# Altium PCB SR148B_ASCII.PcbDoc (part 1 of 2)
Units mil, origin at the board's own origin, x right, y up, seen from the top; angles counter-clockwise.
Board outline 3900 x 2475 mil, 6 copper layers (Top Layer, Signal Layer 1, Signal Layer 2, Signal Layer 3, Signal Layer 4, Bottom Layer), stack 60.536 mil thick; 89 components, 26 nets, 178 pads, 295 vias.
Unrouted connection lines stored in the file: 1.
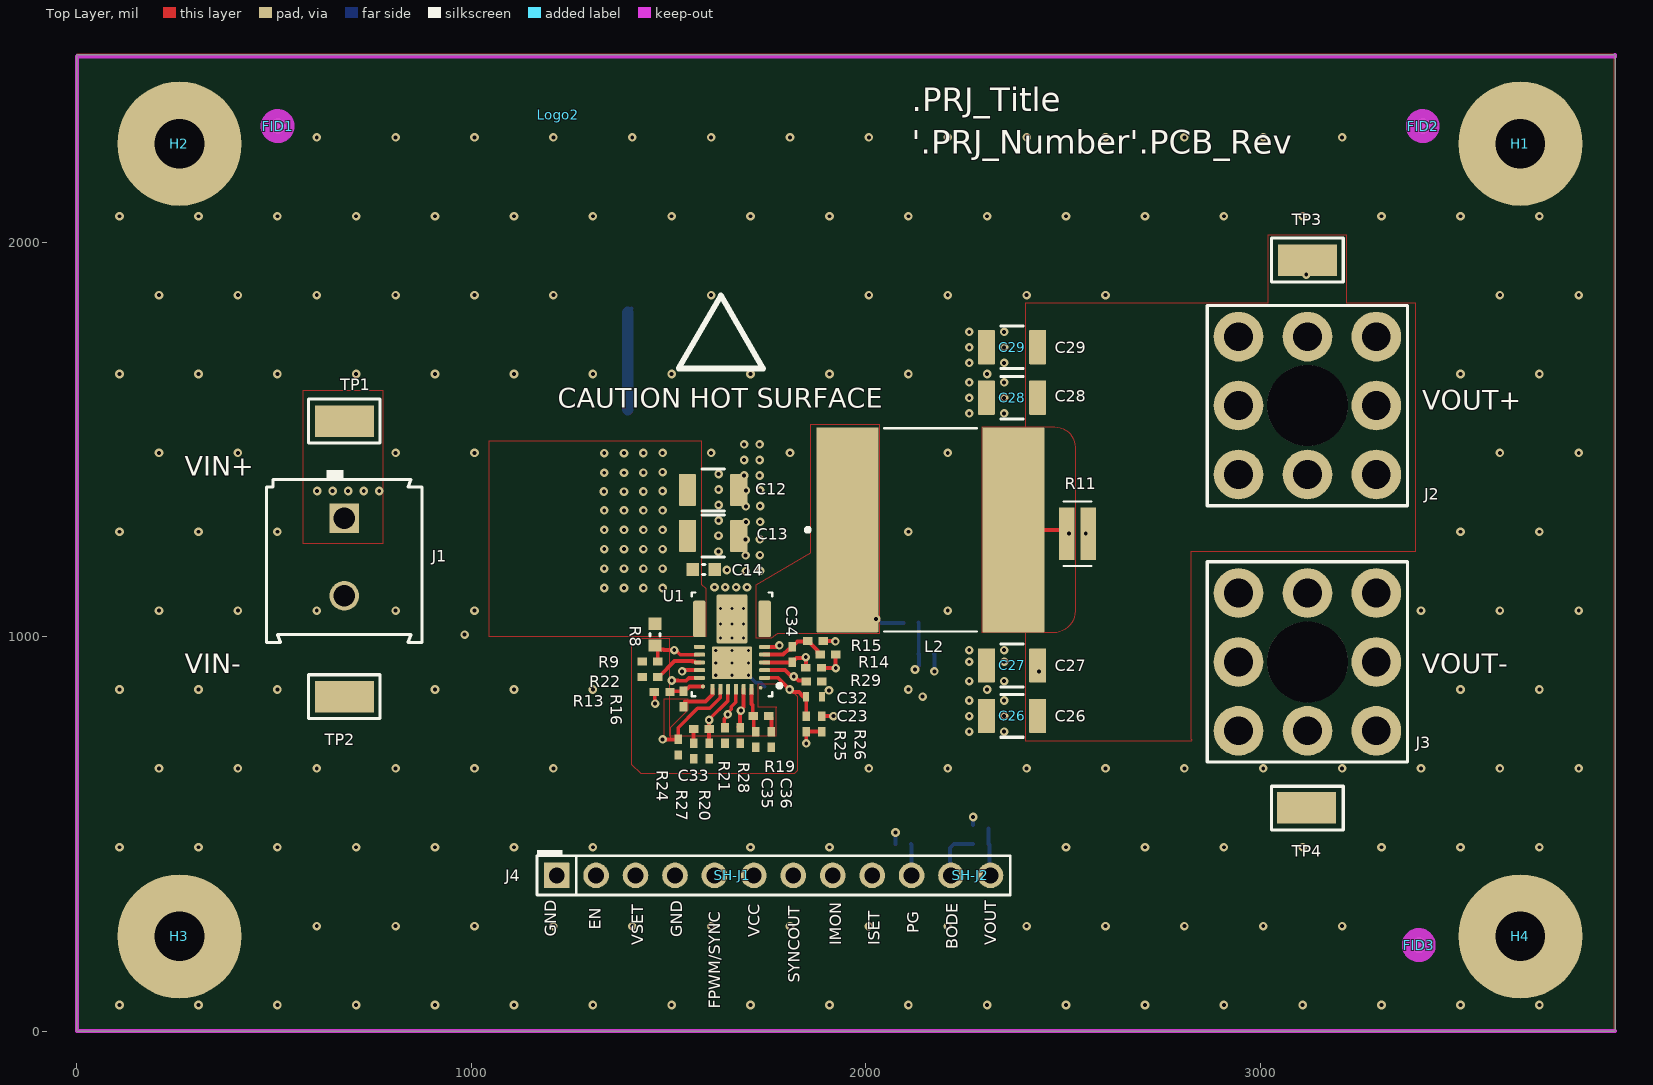
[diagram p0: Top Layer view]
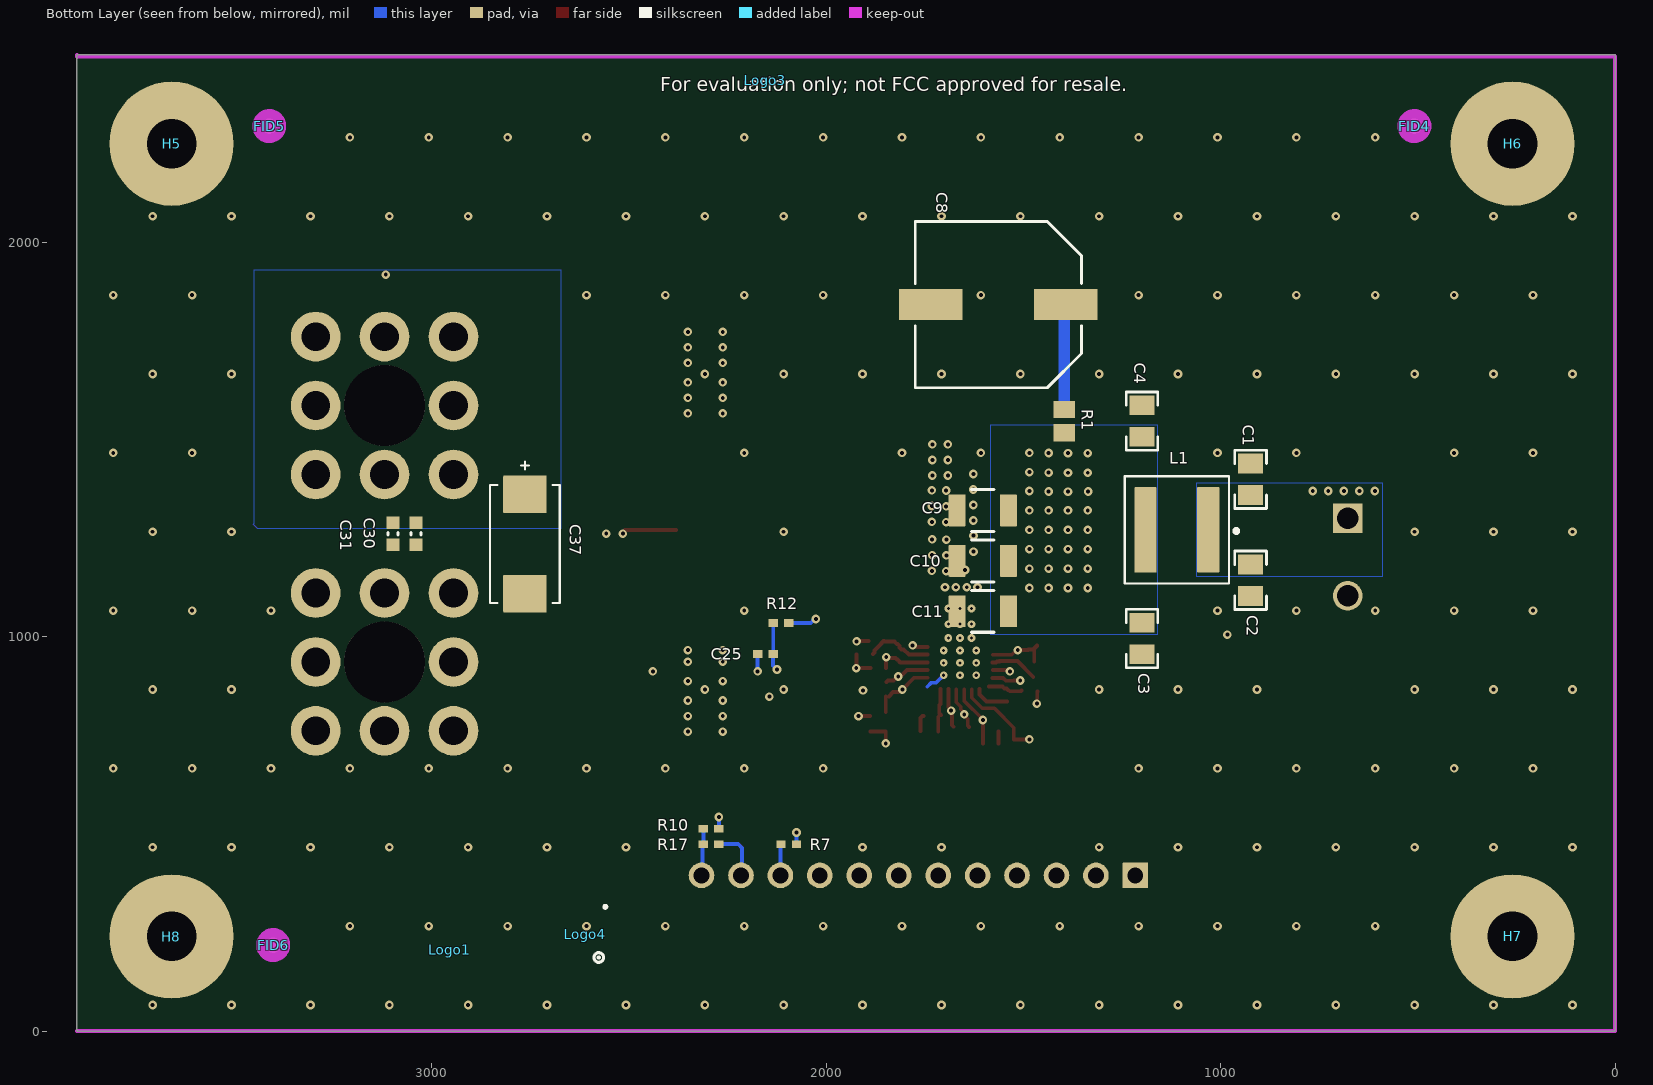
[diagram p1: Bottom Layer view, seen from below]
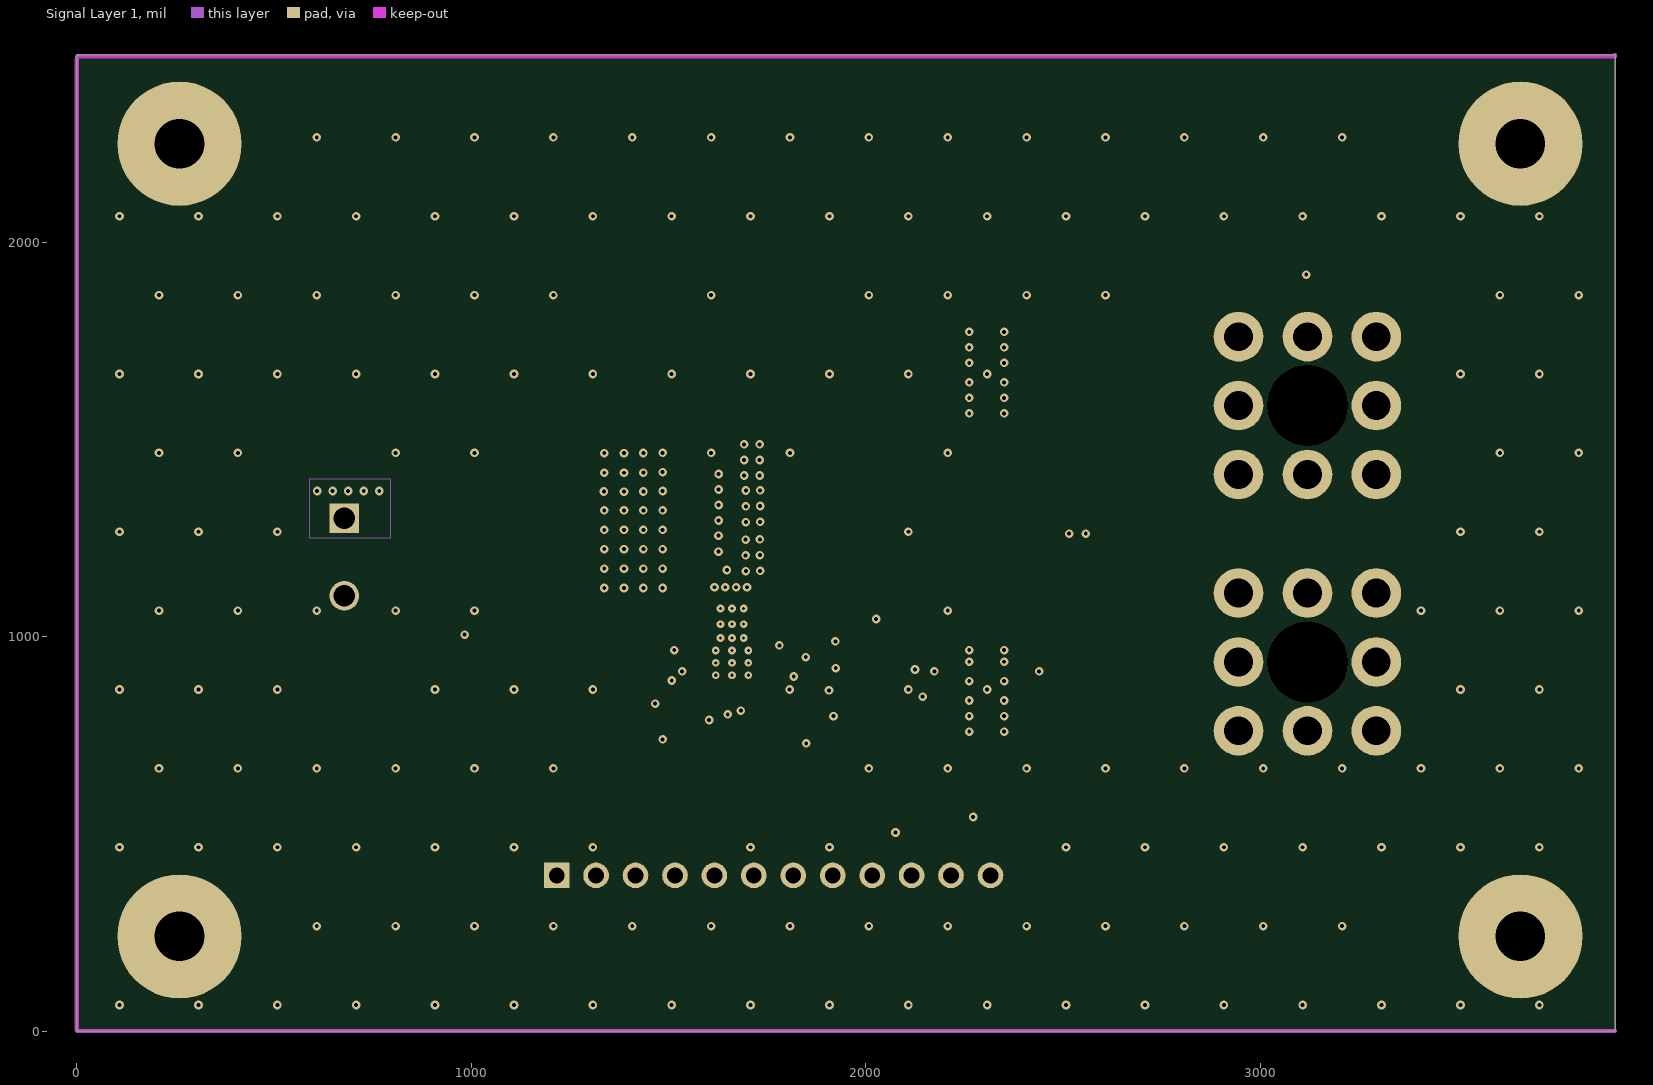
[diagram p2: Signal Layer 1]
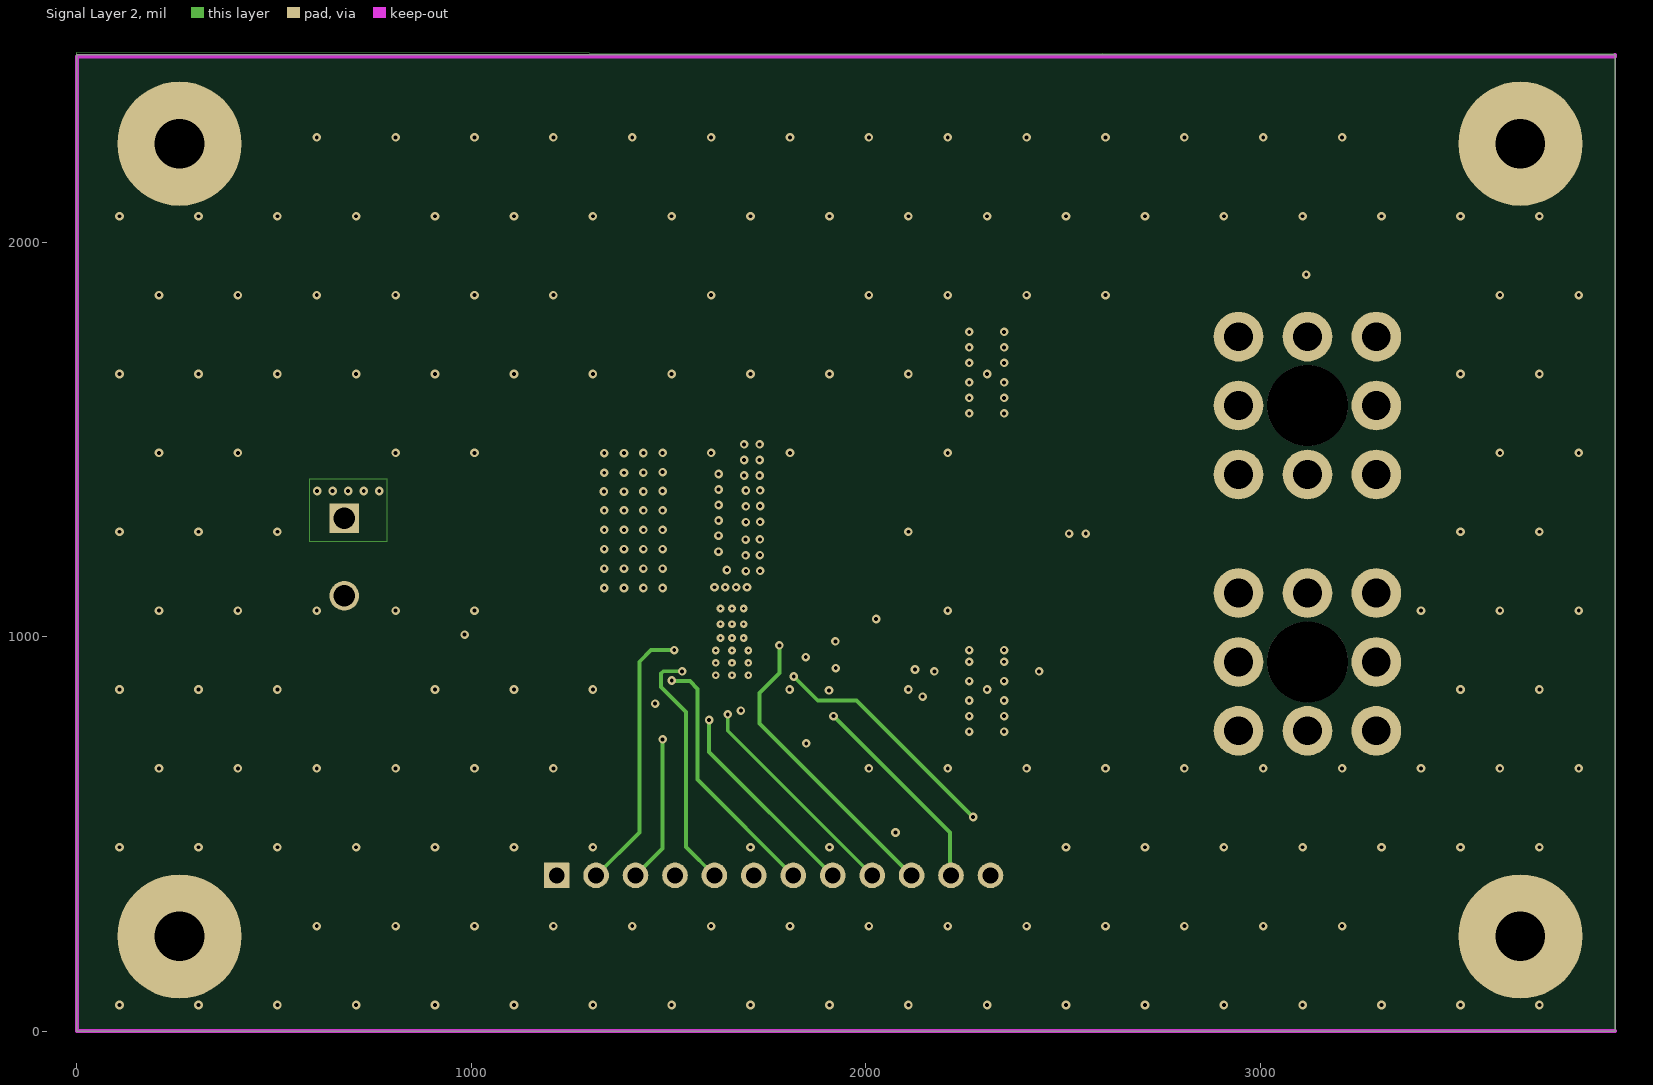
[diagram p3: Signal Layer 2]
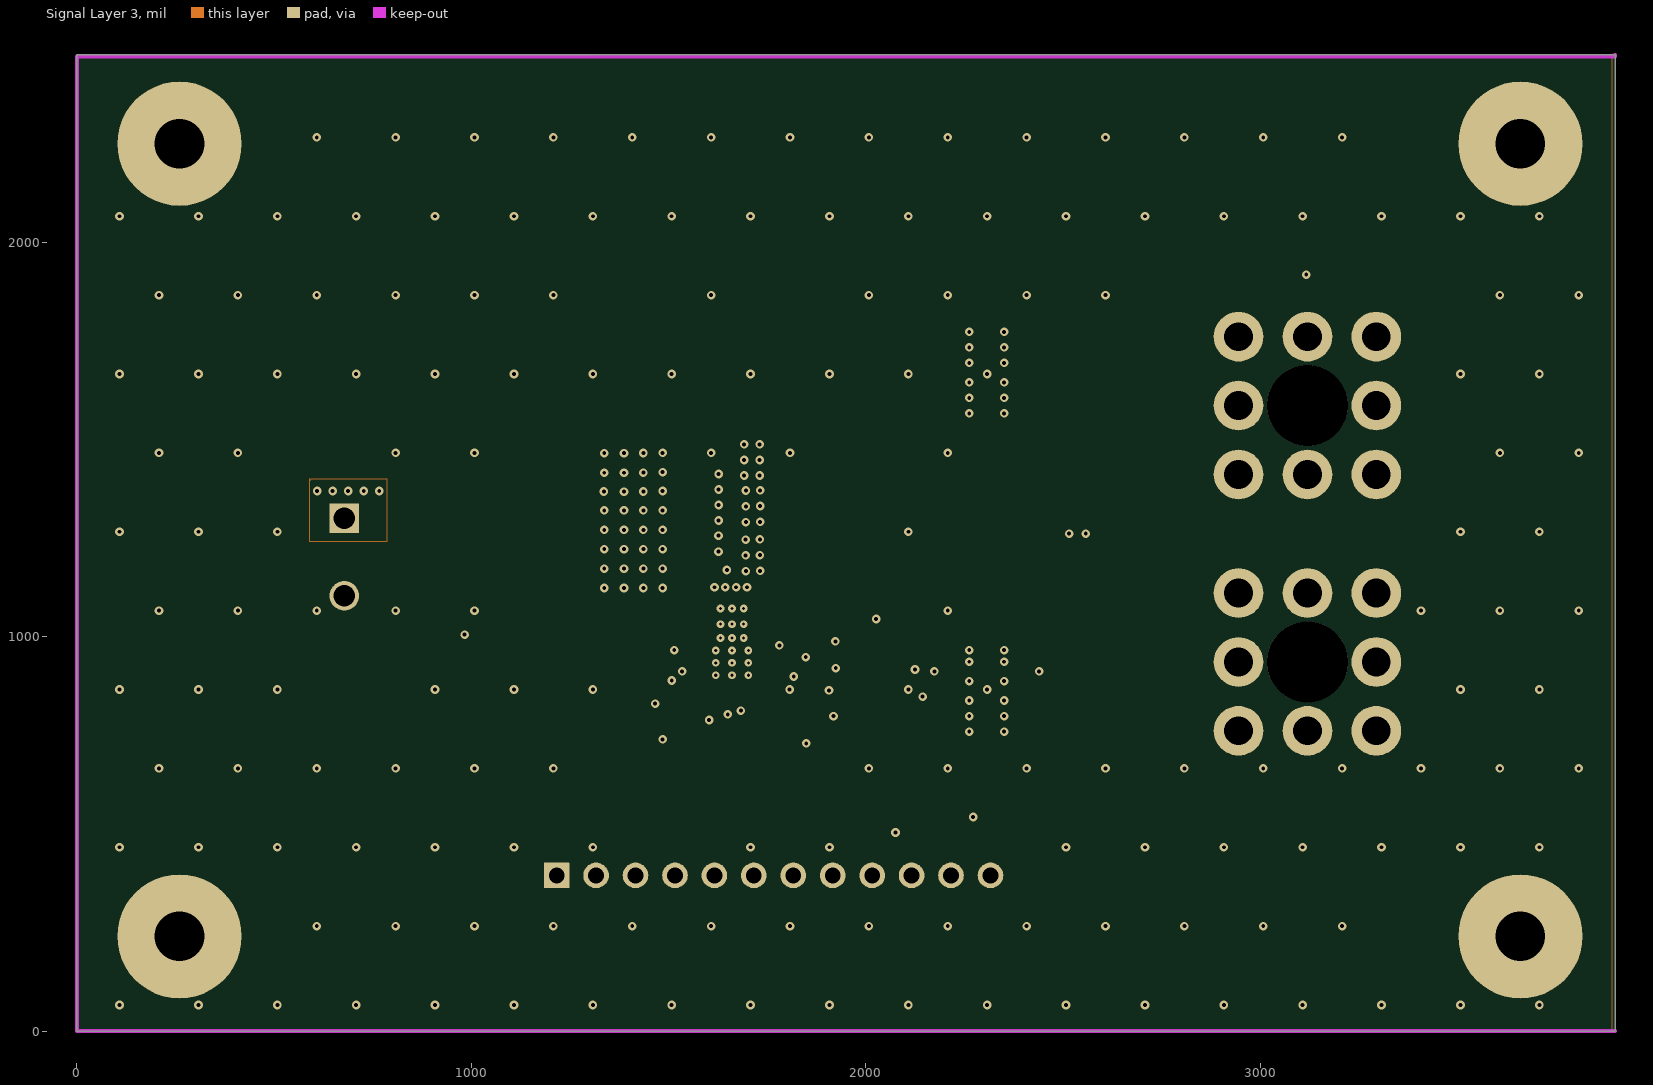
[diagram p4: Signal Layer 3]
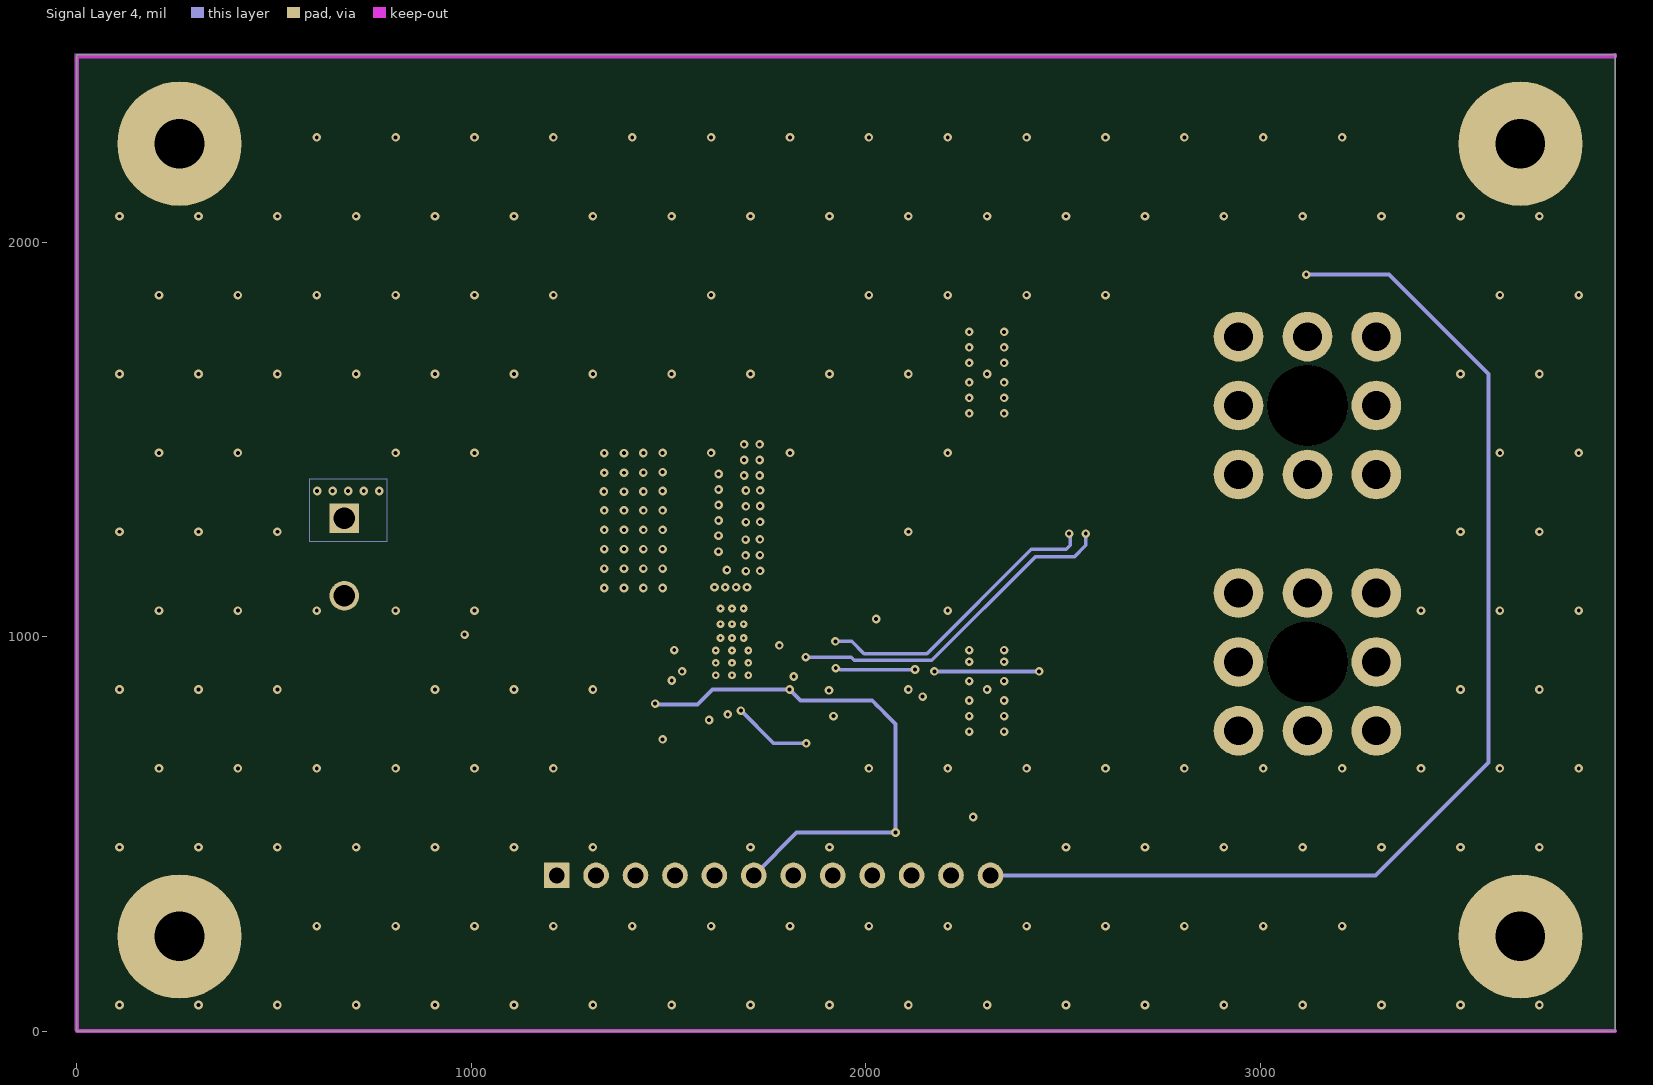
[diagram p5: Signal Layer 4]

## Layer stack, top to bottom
Top Solder: solder mask 0.4, Solder Resist, Dk 3.5
Top Layer: signal copper 2.756
Dielectric 1: prepreg 8, PP-006, Dk 4.1
Signal Layer 1: signal copper 2.756
Dielectric 2: prepreg 8, PP-006, Dk 4.1
Signal Layer 2: signal copper 2.756
Dielectric3: core 12, FR-4 High Tg, Dk 4.8
Signal Layer 3: signal copper 2.756
Dielectric 4: prepreg 8, PP-006, Dk 4.1
Signal Layer 4: signal copper 2.756
Dielectric 5: prepreg 8, PP-006, Dk 4.1
Bottom Layer: signal copper 2.756
Bottom Solder: solder mask 0.4, Solder Resist, Dk 3.5

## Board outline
0,0 3900,0 3900,2475 0,2475

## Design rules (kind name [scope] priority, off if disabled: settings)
AcuteAngle [All] p0: scope1count=1 scope1_0_kind=Board scope1_0_value=Board scope2count=1 scope2_0_kind=Board scope2_0_value=Board commentlength=0 minimum=4.50000000000000E+0001
AcuteAngle [All] p1: minimum=4.50000000000000E+0001 checktracksonly=FALSE
AssemblyTestPointUsage [All] p0: scope1count=1 scope1_0_kind=Board scope1_0_value=Board scope2count=1 scope2_0_kind=Board scope2_0_value=Board commentlength=0
AssemblyTestPointUsage [All] p1: valid=2
AssemblyTestpoint [All] p0: scope1count=1 scope1_0_kind=Board scope1_0_value=Board scope2count=1 scope2_0_kind=Board scope2_0_value=Board commentlength=0
BoardOutlineClearance [All] p0 off: scope1count=1 scope1_0_kind=Board scope1_0_value=Board scope2count=1 scope2_0_kind=Board scope2_0_value=Board commentlength=172 gap=40 // Protel DXP Scope 1 Expression Was: OnCopper and Not InComponentClass('Logo') and not InComponentClass('FiducialMark') and not InRegion(1000,500,4000,800) and not InPoly
BoardOutlineClearance BoardOutlineClearance_Poly [All] p0 off: scope1count=1 scope1_0_kind=Board scope1_0_value=Board scope2count=1 scope2_0_kind=Board scope2_0_value=Board commentlength=58 gap=25 // Protel DXP Scope 1 Expression Was: OnCopper and IsPoly
BoardOutlineClearance BoardOutlineClearance_MountingHoles [All] p0 off: scope1count=1 scope1_0_kind=Board scope1_0_value=Board scope2count=1 scope2_0_kind=Board scope2_0_value=Board commentlength=86 gap=39.37 // Protel DXP Scope 1 Expression Was: OnCopper and InComponentClass('Mounting Holes')
BoardOutlineClearance BoardOutlineClearance_MountingHoles [OnCopper and InComponentClass('Mounting Holes')] p1: gap=39.37 ignorepadtopadclearanceinfootprint=FALSE
BoardOutlineClearance BoardOutlineClearance_Poly [OnCopper and IsPoly] p2: gap=25 ignorepadtopadclearanceinfootprint=FALSE
BoardOutlineClearance [OnCopper and Not InComponentClass('Logo') and not InComponentClass('FiducialMark') and not InRegion(1000,500,4000,800) and not InPoly] p3: gap=40 ignorepadtopadclearanceinfootprint=FALSE
Clearance [All] p0 off: scope1count=1 scope1_0_kind=Board scope1_0_value=Board scope2count=1 scope2_0_kind=Layer scope2_0_value=TOP commentlength=75 gap=10 // Protel DXP Scope 1 Expression Was: InNamedPolygon('TOP_LAYER_GND_P823')
Clearance Clearance_1 [All] p0: scope1count=1 scope1_0_kind=Board scope1_0_value=Board scope2count=1 scope2_0_kind=Board scope2_0_value=Board commentlength=0 gap=7
Clearance Clearance_Keepouts [All] p0 off: scope1count=1 scope1_0_kind=Board scope1_0_value=Board scope2count=1 scope2_0_kind=Board scope2_0_value=Board commentlength=99 gap=10 // Protel DXP Scope 2 Expression Was: ((IsTrack Or IsArc) And Not InPoly) And IsFree and IsKeepOut
Clearance Clearance_Poly [All] p0 off: scope1count=1 scope1_0_kind=Board scope1_0_value=Board scope2count=1 scope2_0_kind=Board scope2_0_value=Board commentlength=48 gap=10 // Protel DXP Scope 1 Expression Was: InPolygon
Clearance Clearance_FiducialMark [All] p0 off: scope1count=1 scope1_0_kind=Board scope1_0_value=Board scope2count=1 scope2_0_kind=Board scope2_0_value=Board commentlength=81 gap=0 // Protel DXP Scope 2 Expression Was: IsPad and InComponentClass('FiducialMark')
Clearance [InNamedPolygon('TOP_LAYER_GND_P823') vs OnLayer('Top Layer')] p1: gap=10 ignorepadtopadclearanceinfootprint=FALSE
Clearance Clearance_FiducialMark [IsKeepOut and InComponentClass('FiducialMark') vs IsPad and InComponentClass('FiducialMark')] p2: gap=0 ignorepadtopadclearanceinfootprint=TRUE
Clearance Clearance_Keepouts [((IsTrack Or IsArc) And Not InPoly) And IsFree and IsKeepOut vs ((IsTrack Or IsArc) And Not InPoly) And IsFree and IsKeepOut] p3: gap=10 ignorepadtopadclearanceinfootprint=TRUE
Clearance Clearance_Poly [InPolygon] p4: gap=10 ignorepadtopadclearanceinfootprint=TRUE
Clearance Clearance_1 [All] p5: gap=7 ignorepadtopadclearanceinfootprint=TRUE except(0: SMDPad-Fill SMDPad-Poly SMDPad-Region)
ComponentClearance [All] p0: scope1count=1 scope1_0_kind=Board scope1_0_value=Board scope2count=1 scope2_0_kind=Board scope2_0_value=Board commentlength=0 gap=0 collisioncheckmode=3
ComponentClearance ComponentClearance_indInput [All] p0: scope1count=1 scope1_0_kind=Footprint scope1_0_value=HC2LP scope2count=1 scope2_0_kind=Footprint scope2_0_value=XAL8080 commentlength=0 gap=0 collisioncheckmode=3
ComponentClearance ComponentClearance_Inductors [All] p0: scope1count=1 scope1_0_kind=Footprint scope1_0_value=SER2915L scope2count=1 scope2_0_kind=Footprint scope2_0_value=IHLP-6767GZ commentlength=0 gap=0 collisioncheckmode=3
ComponentClearance ComponentClearance_MountingHoles_Headers [All] p0: scope1count=1 scope1_0_kind=Footprint scope1_0_value="NY PMS 440 0025 PH" scope2count=1 scope2_0_kind=Footprint scope2_0_value=Keystone_1902E commentlength=0 gap=0 collisioncheckmode=3
ComponentClearance ComponentClearanceConnectors [All] p0: scope1count=1 scope1_0_kind=Footprint scope1_0_value=FP-CB70-14-190_CONN_TERM_RECT_LUG-MFG scope2count=1 scope2_0_kind=Footprint scope2_0_value=Keystone_6096 commentlength=0 gap=0 collisioncheckmode=3
ComponentClearance ComponentClearance_THtoTH [All] p0 off: scope1count=1 scope1_0_kind=Board scope1_0_value=Board scope2count=1 scope2_0_kind=Board scope2_0_value=Board commentlength=54 gap=20 collisioncheckmode=3 // Protel DXP Scope 2 Expression Was: IsThruComponent
ComponentClearance ComponentClearance_THtoSMT [All] p0 off: scope1count=1 scope1_0_kind=Board scope1_0_value=Board scope2count=1 scope2_0_kind=Board scope2_0_value=Board commentlength=53 gap=0 collisioncheckmode=3 // Protel DXP Scope 2 Expression Was: IsSMTComponent
ComponentClearance ComponentClearance_SmallPassives [All] p0 off: scope1count=1 scope1_0_kind=Board scope1_0_value=Board scope2count=1 scope2_0_kind=Board scope2_0_value=Board commentlength=508 gap=10 collisioncheckmode=3 // Protel DXP Scope 2 Expression Was: HasFootprint('0201*') or HasFootprint('0402*') or HasFootprint('0508') or HasFootprint('0603*') or HasFootprint('0612') or HasFootprint('0805*') or HasFootprint('0815*') or HasFootprint('0830*') or HasFootprint('1206*') or HasFootprint('1210*') or HasFootprint('1808*') or HasFootprint('1812*') or HasFootprint('1825*') or HasFootprint('2010*') or HasFootprint('2220*') or HasFootprint('2225*') or HasFootprint('2512*') or HasFootprint('2728*') or HasFootprint('3518*')
ComponentClearance ComponentClearance_MountingHoles [All] p0: scope1count=1 scope1_0_kind=ComponentClass scope1_0_value="Mounting Holes" scope2count=1 scope2_0_kind=ComponentClass scope2_0_value="Mounting Holes" commentlength=0 gap=100 collisioncheckmode=3
ComponentClearance ComponentClearance_ScrewToNut [All] p0 off: scope1count=1 scope1_0_kind=Board scope1_0_value=Board scope2count=1 scope2_0_kind=Board scope2_0_value=Board commentlength=71 gap=5 collisioncheckmode=3 // Protel DXP Scope 2 Expression Was: (HasFootprint('Keystone_1902C'))
ComponentClearance ComponentClearance_Logo [All] p0: scope1count=1 scope1_0_kind=ComponentClass scope1_0_value=Logo scope2count=1 scope2_0_kind=Board scope2_0_value=Board commentlength=0 gap=30 collisioncheckmode=3
ComponentClearance ComponentClearance_Shunt [All] p0: scope1count=1 scope1_0_kind=ComponentClass scope1_0_value=Header scope2count=1 scope2_0_kind=ComponentClass scope2_0_value=Shunt commentlength=0 gap=0 collisioncheckmode=3
ComponentClearance ComponentClearance_MountingHoles_FiducialMarks [All] p0: scope1count=1 scope1_0_kind=ComponentClass scope1_0_value="Mounting Holes" scope2count=1 scope2_0_kind=ComponentClass scope2_0_value=FiducialMark commentlength=0 gap=50 collisioncheckmode=3
ComponentClearance ComponentClearance_MountingHoles_FiducialMarks [InComponentClass('Mounting Holes') vs InComponentClass('FiducialMark')] p1: gap=50 collisioncheckmode=3 verticalgap=10 showdistances=FALSE
ComponentClearance ComponentClearance_Shunt [InComponentClass('Header') vs InComponentClass('Shunt')] p2: gap=0 collisioncheckmode=3 verticalgap=0 showdistances=FALSE
ComponentClearance ComponentClearance_Logo [InComponentClass('Logo')] p3: gap=30 collisioncheckmode=3 verticalgap=10 showdistances=FALSE
ComponentClearance ComponentClearance_ScrewToNut [(HasFootprint('NY PMS 440 0025 PH')) vs (HasFootprint('Keystone_1902C'))] p4: gap=5 collisioncheckmode=3 verticalgap=10 showdistances=FALSE
ComponentClearance ComponentClearance_MountingHoles_Headers [HasFootprint('NY PMS 440 0025 PH') vs HasFootprint('Keystone_1902E')] p5: gap=0 collisioncheckmode=3 verticalgap=0 showdistances=FALSE
ComponentClearance ComponentClearance_MountingHoles [InComponentClass('Mounting Holes') vs InComponentClass('Mounting Holes')] p6: gap=100 collisioncheckmode=3 verticalgap=0 showdistances=FALSE
ComponentClearance ComponentClearance_SmallPassives [HasFootprint('0201*') or HasFootprint('0402*') or HasFootprint('0508') or HasFootprint('0603*') or HasFootprint('0612') or HasFootprint('0805*') or HasFootprint('0815*') or HasFootprint('0830*') or HasFootprint('1206*') or HasFootprint('1210*') or HasFootprint('1808*') or HasFootprint('1812*') or HasFootprint('1825*') or HasFootprint('2010*') or HasFootprint('2220*') or HasFootprint('2225*') or HasFootprint('2512*') or HasFootprint('2728*') or HasFootprint('3518*') vs HasFootprint('0201*') or HasFootprint('0402*') or HasFootprint('0508') or HasFootprint('0603*') or HasFootprint('0612') or HasFootprint('0805*') or HasFootprint('0815*') or HasFootprint('0830*') or HasFootprint('1206*') or HasFootprint('1210*') or HasFootprint('1808*') or HasFootprint('1812*') or HasFootprint('1825*') or HasFootprint('2010*') or HasFootprint('2220*') or HasFootprint('2225*') or HasFootprint('2512*') or HasFootprint('2728*') or HasFootprint('3518*')] p7: gap=10 collisioncheckmode=3 verticalgap=10 showdistances=FALSE
ComponentClearance ComponentClearance_THtoSMT [IsThruComponent vs IsSMTComponent] p8: gap=0 collisioncheckmode=3 verticalgap=0 showdistances=FALSE
ComponentClearance ComponentClearanceConnectors [HasFootprint('FP-CB70-14-190_CONN_TERM_RECT_LUG-MFG') vs HasFootprint('Keystone_6096')] p9: gap=0 collisioncheckmode=3 verticalgap=0 showdistances=FALSE
ComponentClearance ComponentClearance_Inductors [HasFootprint('SER2915L') vs HasFootprint('IHLP-6767GZ')] p10: gap=0 collisioncheckmode=3 verticalgap=0 showdistances=FALSE
ComponentClearance ComponentClearance_indInput [HasFootprint('HC2LP') vs HasFootprint('XAL8080')] p11: gap=0 collisioncheckmode=3 verticalgap=0 showdistances=FALSE
ComponentClearance ComponentClearance_THtoTH [IsThruComponent vs IsThruComponent] p12: gap=20 collisioncheckmode=3 verticalgap=30 showdistances=FALSE
ComponentClearance [All] p13: gap=0 collisioncheckmode=3 verticalgap=0 showdistances=TRUE
DiffPairsRouting [All] p0: scope1count=1 scope1_0_kind=Board scope1_0_value=Board scope2count=1 scope2_0_kind=Board scope2_0_value=Board commentlength=0
DiffPairsRouting [All] p1: maxlimit=100 minlimit=10 mostfreqgap=10 toplayer_minwidth=15 toplayer_maxwidth=15 toplayer_prefwidth=15 midlayer1_minwidth=15 midlayer1_maxwidth=15 midlayer1_prefwidth=15 midlayer2_minwidth=15 midlayer2_maxwidth=15 midlayer2_prefwidth=15 midlayer3_minwidth=15 midlayer3_maxwidth=15 midlayer3_prefwidth=15 midlayer4_minwidth=15 midlayer4_maxwidth=15 midlayer4_prefwidth=15 bottomlayer_minwidth=15 bottomlayer_maxwidth=15 bottomlayer_prefwidth=15 maxuncoupledlength=1000
FabricationTestPointUsage TestPointUsage [All] p0: scope1count=1 scope1_0_kind=Board scope1_0_value=Board scope2count=1 scope2_0_kind=Board scope2_0_value=Board commentlength=0 valid=2 allowmultiple=FALSE
FabricationTestPointUsage TestPointUsage [All] p1: valid=2 allowmultiple=FALSE
FabricationTestpoint Testpoint [All] p0: scope1count=1 scope1_0_kind=Board scope1_0_value=Board scope2count=1 scope2_0_kind=Board scope2_0_value=Board commentlength=0 side=3 testpointundercomponent=TRUE minsize=40 maxsize=100 preferedsize=60 minholesize=0 maxholesize=40 preferedholesize=32 testpointgrid=1
FabricationTestpoint Testpoint [All] p1: side=3 testpointundercomponent=TRUE minsize=40 maxsize=100 preferedsize=60 minholesize=0 maxholesize=40 preferedholesize=32 testpointgrid=1 allowsidetop=TRUE allowsidebottom=TRUE usegrid=TRUE gridtolerance=0.01
FanoutControl Fanout_Small [All] p0 off: scope1count=1 scope1_0_kind=Board scope1_0_value=Board scope2count=1 scope2_0_kind=Board scope2_0_value=Board commentlength=84 // Protel DXP Scope 1 Expression Was: (CompPinCount < 5)   Fanout_Small (Default Rule)
FanoutControl Fanout_Default [All] p0: scope1count=1 scope1_0_kind=Board scope1_0_value=Board scope2count=1 scope2_0_kind=Board scope2_0_value=Board commentlength=30 // Fanout_Default (Default Rule)
FanoutControl Fanout_SOIC [All] p0 off: scope1count=1 scope1_0_kind=Board scope1_0_value=Board scope2count=1 scope2_0_kind=Board scope2_0_value=Board commentlength=71 // Protel DXP Scope 1 Expression Was: IsSOIC   Fanout_SOIC (Default Rule)
FanoutControl Fanout_BGA [All] p0 off: scope1count=1 scope1_0_kind=Board scope1_0_value=Board scope2count=1 scope2_0_kind=Board scope2_0_value=Board commentlength=69 // Protel DXP Scope 1 Expression Was: IsBGA   Fanout_BGA (Default Rule)
FanoutControl Fanout_LCC [All] p0 off: scope1count=1 scope1_0_kind=Board scope1_0_value=Board scope2count=1 scope2_0_kind=Board scope2_0_value=Board commentlength=69 // Protel DXP Scope 1 Expression Was: IsLCC   Fanout_LCC (Default Rule)
FanoutControl Fanout_LCC [IsLCC] p1: bgadir=Out bgaviamode=Centered fanoutstyle=Auto fanoutdirection=Alternating viagrid=1 // Fanout_LCC (Default Rule)
FanoutControl Fanout_BGA [IsBGA] p2: bgadir=Out bgaviamode=Centered fanoutstyle=Auto fanoutdirection=Alternating viagrid=1 // Fanout_BGA (Default Rule)
Height [All] p0: scope1count=1 scope1_0_kind=Board scope1_0_value=Board scope2count=1 scope2_0_kind=Board scope2_0_value=Board commentlength=0
Height [All] p1: minheight=0 maxheight=1500 prefheight=500
HoleSize [All] p0: scope1count=1 scope1_0_kind=Board scope1_0_value=Board scope2count=1 scope2_0_kind=Board scope2_0_value=Board commentlength=0 absolutevalues=TRUE maxlimit=300 minlimit=7.87 maxpercent=80.000 minpercent=20.000
HoleSize [All] p1: absolutevalues=TRUE maxlimit=300 minlimit=7.87 maxpercent=80.000 minpercent=20.000
HoleToHoleClearance [All] p0: scope1count=1 scope1_0_kind=Board scope1_0_value=Board scope2count=1 scope2_0_kind=Board scope2_0_value=Board commentlength=0
LayerPairs [All] p0: scope1count=1 scope1_0_kind=Board scope1_0_value=Board scope2count=1 scope2_0_kind=Board scope2_0_value=Board commentlength=0 enforce=TRUE
MinimumAnnularRing [All] p0: scope1count=1 scope1_0_kind=Board scope1_0_value=Board scope2count=1 scope2_0_kind=Board scope2_0_value=Board commentlength=0 minimumring=0
MinimumAnnularRing MinimumAnnularRing_ThermalPadVias [All] p0 off: scope1count=1 scope1_0_kind=Board scope1_0_value=Board scope2count=1 scope2_0_kind=Board scope2_0_value=Board commentlength=63 minimumring=5.91 // Protel DXP Scope 1 Expression Was: IsVia and InAnyComponent
MinimumAnnularRing MinimumAnnularRing_ThermalPadVias [IsVia and InAnyComponent] p1: minimumring=5.91
MinimumAnnularRing [All] p2: minimumring=0
MinimumSolderMaskSliver [All] p0: scope1count=1 scope1_0_kind=Board scope1_0_value=Board scope2count=1 scope2_0_kind=Board scope2_0_value=Board commentlength=0
MinimumSolderMaskSliver MinimumSolderMaskSliver_Logo [All] p0: scope1count=1 scope1_0_kind=ComponentClass scope1_0_value=Logo scope2count=1 scope2_0_kind=ComponentClass scope2_0_value=Logo commentlength=0
MinimumSolderMaskSliver MinimumSolderMaskSliver_Logo [InComponentClass('Logo') vs InComponentClass('Logo')] p1: minsoldermaskwidth=0.7
MinimumSolderMaskSliver [All] p2: minsoldermaskwidth=3.94
NetAntennae [All] p0: scope1count=1 scope1_0_kind=Board scope1_0_value=Board scope2count=1 scope2_0_kind=Board scope2_0_value=Board commentlength=0
PasteMaskExpansion [All] p0: scope1count=1 scope1_0_kind=Board scope1_0_value=Board scope2count=1 scope2_0_kind=Board scope2_0_value=Board commentlength=0 expansion=0
PlaneClearance [All] p0: scope1count=1 scope1_0_kind=Board scope1_0_value=Board scope2count=1 scope2_0_kind=Board scope2_0_value=Board commentlength=0 clearance=10
PlaneClearance [All] p1: clearance=10
PlaneConnect [All] p0: scope1count=1 scope1_0_kind=Board scope1_0_value=Board scope2count=1 scope2_0_kind=Board scope2_0_value=Board commentlength=0 planeconnectstyle=Direct reliefexpansion=10 reliefentries=4 reliefconductorwidth=10 reliefairgap=10
PlaneConnect [All] p1: planeconnectstyle=Direct reliefexpansion=10 reliefentries=4 reliefconductorwidth=10 reliefairgap=10
PolygonConnect PolygonConnectStyle_1 [All] p0: scope1count=1 scope1_0_kind=Footprint scope1_0_value=TSW-112-07-G-S scope2count=1 scope2_0_kind=Board scope2_0_value=Board commentlength=0 connectstyle=Direct reliefconductorwidth=10 reliefentries=4 polygonreliefangle="90 Angle"
PolygonConnect [All] p0: scope1count=1 scope1_0_kind=Board scope1_0_value=Board scope2count=1 scope2_0_kind=Board scope2_0_value=Board commentlength=0 connectstyle=Direct reliefconductorwidth=10 reliefentries=4 polygonreliefangle="90 Angle"
PolygonConnect PolygonConnectStyle_1 [HasFootprint('TSW-112-07-G-S')] p1: connectstyle=Direct reliefconductorwidth=10 reliefentries=4 polygonreliefangle="90 Angle" airgapwidth=10
PolygonConnect [All] p2: connectstyle=Direct reliefconductorwidth=10 reliefentries=4 polygonreliefangle="90 Angle" airgapwidth=10
RoutingCorners [All] p0: scope1count=1 scope1_0_kind=Board scope1_0_value=Board scope2count=1 scope2_0_kind=Board scope2_0_value=Board commentlength=0 cornerstyle=45-Degree minsetback=100 maxsetback=100
RoutingLayers [All] p0: scope1count=1 scope1_0_kind=Board scope1_0_value=Board scope2count=1 scope2_0_kind=Board scope2_0_value=Board commentlength=0 top layer=Automatic mid layer 1=Automatic mid layer 2=Automatic mid layer 3=Automatic mid layer 4=Automatic bottom layer=Automatic
RoutingPriority [All] p0: scope1count=1 scope1_0_kind=Board scope1_0_value=Board scope2count=1 scope2_0_kind=Board scope2_0_value=Board commentlength=0
RoutingTopology [All] p0: scope1count=1 scope1_0_kind=Board scope1_0_value=Board scope2count=1 scope2_0_kind=Board scope2_0_value=Board commentlength=0 topology=Shortest
RoutingVias [All] p0: scope1count=1 scope1_0_kind=Board scope1_0_value=Board scope2count=1 scope2_0_kind=Board scope2_0_value=Board commentlength=0 holewidth=10 width=22 viastyle="Through Hole" minholewidth=7.87 minwidth=20 maxholewidth=40 maxwidth=65
RoutingVias ThermalPadVias [All] p0 off: scope1count=1 scope1_0_kind=Board scope1_0_value=Board scope2count=1 scope2_0_kind=Board scope2_0_value=Board commentlength=63 holewidth=7.87 width=19.68 viastyle="Through Hole" minholewidth=7.87 minwidth=19.68 maxholewidth=16 maxwidth=32 // Protel DXP Scope 1 Expression Was: IsVia and InAnyComponent
RoutingVias ThermalPadVias [IsVia and InAnyComponent] p1: holewidth=7.87 width=19.68 viastyle="Through Hole" minholewidth=7.87 minwidth=19.68 maxholewidth=16 maxwidth=32
RoutingVias [All] p2: holewidth=10 width=22 viastyle="Through Hole" minholewidth=7.87 minwidth=20 maxholewidth=40 maxwidth=65
ShortCircuit [All] p0: scope1count=1 scope1_0_kind=Net scope1_0_value=VOUT scope2count=1 scope2_0_kind=Net scope2_0_value=VOUT commentlength=0 allowed=TRUE
ShortCircuit [InNet('VOUT') vs InNet('VOUT')] p1: allowed=TRUE
SilkToBoardRegionClearance [All] p0: scope1count=1 scope1_0_kind=Board scope1_0_value=Board scope2count=1 scope2_0_kind=Board scope2_0_value=Board commentlength=0
SilkToSilkClearance [All] p0: scope1count=1 scope1_0_kind=Board scope1_0_value=Board scope2count=1 scope2_0_kind=Board scope2_0_value=Board commentlength=0
SilkToSilkClearance SilkToSilkClearance_Pb-FreeLogo [All] p0 off: scope1count=1 scope1_0_kind=Board scope1_0_value=Board scope2count=1 scope2_0_kind=Board scope2_0_value=Board commentlength=120 // Protel DXP Scope 2 Expression Was: (HasFootprint('Pb-Free_Overlay_Medium') OR HasFootprint('Pb-Free_Overlay_Small'))
SilkToSilkClearance SilkToSilkClearance_Pb-FreeLogo [(HasFootprint('Pb-Free_Overlay_Medium') OR HasFootprint('Pb-Free_Overlay_Small')) vs (HasFootprint('Pb-Free_Overlay_Medium') OR HasFootprint('Pb-Free_Overlay_Small'))] p1: silktosilkclearance=0
SilkToSilkClearance [All] p2: silktosilkclearance=3.94
SilkToSolderMaskClearance "Silk to Solder Mask Opening" [All] p0: scope1count=1 scope1_0_kind=Board scope1_0_value=Board scope2count=1 scope2_0_kind=Board scope2_0_value=Board commentlength=0
SilkToSolderMaskClearance SilkToComponentPadClearance [All] p0 off: scope1count=1 scope1_0_kind=Board scope1_0_value=Board scope2count=1 scope2_0_kind=Board scope2_0_value=Board commentlength=87 // Protel DXP Scope 1 Expression Was: (IsPad or IsFill or IsRegion) and InAnycomponent
SilkToSolderMaskClearance SilkToComponentPadClearance [(IsPad or IsFill or IsRegion) and InAnycomponent] p1: minsilkscreentomaskgap=5 clearancetoexposedcopper=TRUE
SilkToSolderMaskClearance "Silk to Solder Mask Opening" [All] p2: minsilkscreentomaskgap=3.94 clearancetoexposedcopper=FALSE
SolderMaskExpansion [All] p0: scope1count=1 scope1_0_kind=Board scope1_0_value=Board scope2count=1 scope2_0_kind=Board scope2_0_value=Board commentlength=0 expansion=1.97
SolderMaskExpansion [All] p1: expansion=1.97 istentingtop=FALSE
SupplyNets "Schematic Supply Nets_4" [All] p0: scope1count=1 scope1_0_kind=Net scope1_0_value=VIN scope2count=1 scope2_0_kind=Board scope2_0_value=Board commentlength=0 voltage=0.000
SupplyNets "Schematic Supply Nets_3" [All] p0: scope1count=1 scope1_0_kind=Net scope1_0_value=VCC scope2count=1 scope2_0_kind=Board scope2_0_value=Board commentlength=0 voltage=0.000
SupplyNets "Schematic Supply Nets_2" [All] p0: scope1count=1 scope1_0_kind=Net scope1_0_value=VOUT scope2count=1 scope2_0_kind=Board scope2_0_value=Board commentlength=0 voltage=0.000
SupplyNets "Schematic Supply Nets_1" [All] p0: scope1count=1 scope1_0_kind=Net scope1_0_value=AGND scope2count=1 scope2_0_kind=Board scope2_0_value=Board commentlength=0 voltage=0.000
SupplyNets "Schematic Supply Nets" [All] p0: scope1count=1 scope1_0_kind=Net scope1_0_value=GND scope2count=1 scope2_0_kind=Board scope2_0_value=Board commentlength=0 voltage=0.000
SupplyNets "Schematic Supply Nets_4" [InNet('VIN')] p1: voltage=0.000
SupplyNets "Schematic Supply Nets_3" [InNet('VCC')] p2: voltage=0.000
SupplyNets "Schematic Supply Nets_2" [InNet('VOUT')] p3: voltage=0.000
SupplyNets "Schematic Supply Nets_1" [InNet('AGND')] p4: voltage=0.000
SupplyNets "Schematic Supply Nets" [InNet('GND')] p5: voltage=0.000
UnRoutedNet [All] p0: scope1count=1 scope1_0_kind=Net scope1_0_value=PGND scope2count=1 scope2_0_kind=Board scope2_0_value=Board commentlength=0
UnRoutedNet [InNet('PGND')] p1: checkbadconnections=TRUE
UnpouredPolygon [All] p0: scope1count=1 scope1_0_kind=Board scope1_0_value=Board scope2count=1 scope2_0_kind=Board scope2_0_value=Board commentlength=0
Width [All] p0: scope1count=1 scope1_0_kind=Board scope1_0_value=Board scope2count=1 scope2_0_kind=Board scope2_0_value=Board commentlength=0 maxlimit=100 minlimit=6 preferedwidth=10
Width [All] p1: maxlimit=100 minlimit=6 preferedwidth=10 checkconnectedcopper=TRUE
14 further rules are at their usual default settings.

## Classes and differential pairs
component class FiducialMark: FID1 FID2 FID3 FID4 FID5 FID6
component class "Mounting Holes": H1 H2 H3 H4
component class Logo: Logo2
component class SR148B_Hardware: !PCB1 "CAUTION HOT SURFACE" FID1 FID2 FID3 FID4 FID5 FID6 H1 H2 H3 H4 H5 H6 H7 H8 Logo1 Logo2 Logo3 Logo4 SH-J1 SH-J2 ZZ1 ZZ2 ZZ3 ZZ4 ZZ5 ZZ6
component class AssemblyNote: ZZ1 ZZ2 ZZ3 ZZ4 ZZ5 ZZ6
component class SR148B: C1 C2 C3 C4 C8 C9 C10 C11 C12 C13 C14 C23 C25 C26 C27 C28 C29 C30 C31 C32 C33 C34 C35 C36 C37 J1 J2 J3 J4 L1 L2 R1 R7 R8 R9 R10 R11 R12 R13 R14 R15 R16 R17 R19 R20 R21 R22 R24 R25 R26 R27 R28 R29 TP1 TP2 TP3 TP4 U1 U2_S1
component class Header: J4

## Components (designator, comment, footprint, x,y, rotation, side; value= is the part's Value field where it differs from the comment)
C1 "GRM21BR72A474KA73L" 0805_HV 924,1398.95 r90 bottom
C2 "GRM21BR72A474KA73L" 0805_HV 924,1143.05 r270 bottom
C3 "GRM21BR72A474KA73L" 0805_HV 1199.59,995.41 r270 bottom
C4 "GRM21BR72A474KA73L" 0805_HV 1199.59,1546.59 r90 bottom
C8 "EEE-FK2A330P" SM_RADIAL_G 1563.76,1841.87 r0 bottom
C9 "GRM32EC72A106KE05L" FP-GRM32EC72A106KE05L_1210-MFG 1603.13,1320.21 r0 bottom
C10 "GRM32EC72A106KE05L" FP-GRM32EC72A106KE05L_1210-MFG 1603.13,1192.26 r0 bottom
C11 "GRM32EC72A106KE05L" FP-GRM32EC72A106KE05L_1210-MFG 1603.13,1064.31 r0 bottom
C12 "GRM32EC72A106KE05L" FP-GRM32EC72A106KE05L_1210-MFG 1613,1372 r0 top
C13 "GRM32EC72A106KE05L" FP-GRM32EC72A106KE05L_1210-MFG 1613,1255.53 r0 top
C14 "CGA3E2X8R2A103K080AD" 0603L 1589.29,1169.94 r0 top
C23 "GRT155C71A225KE13" 0402_070 1868.88,847.77 r0 top
C25 "CGA2B3X7R1E104K050BB" 0402L 2154,956.04 r0 bottom
C26 "GCM32EC71A476KE02K" FP-GCM32EC71A476KE02K_1210-MFG 2371,799 r0 top
C26 "CGA6P3X7R1E226M250AB" FP-CGA6P3X7R1E226M250AB_1210-MFG 2371,799 r0 top
C27 "GCM32EC71A476KE02K" FP-GCM32EC71A476KE02K_1210-MFG 2371,927 r0 top
C27 "CGA6P3X7R1E226M250AB" FP-CGA6P3X7R1E226M250AB_1210-MFG 2371,927 r0 top
C28 "CGA6P3X7R1E226M250AB" FP-CGA6P3X7R1E226M250AB_1210-MFG 2371,1606 r0 top
C28 "GCM32EC71A476KE02K" FP-GCM32EC71A476KE02K_1210-MFG 2371,1606 r0 top
C29 "CGA6P3X7R1E226M250AB" FP-CGA6P3X7R1E226M250AB_1210-MFG 2371,1734 r0 top
C29 "GCM32EC71A476KE02K" FP-GCM32EC71A476KE02K_1210-MFG 2371,1734 r0 top
C30 "C0603C104K5RACTU" 0603L 3040,1261 r270 bottom
C31 "C0603C104K5RACTU" 0603L 3099,1261 r270 bottom
C32 "CGA2B3X7R1E104K050BB" 0402L 1869,886 r0 top
C33 "CGA2B3X8R1H103K050BB" 0402L 1583.45,766 r0 top
C34 "CGA2B2C0G1H101J050BA" 0402L 1814,955 r270 top
C35 "CGA2B2C0G1H470J050BA" 0402L 1721,739.5 r270 top
C36 "GRM155R71H272KA01D" 0402L 1760.61,739.5 r270 top
C37 "ECASD61C107M012KA0" FP-ECASD61C107M012KA0_2917-MFG 2764,1235 r90 bottom
"CAUTION HOT SURFACE" "CAUTION HOT SURFACE" IEC_HotSurface_Small 1632.66,1772.97 r0 top
FID1 "Fiducial" Fiducial10-20 508.78,2294.74 r90 top
FID2 "Fiducial" Fiducial10-20 3412.32,2294.74 r90 top
FID3 "Fiducial" Fiducial10-20 3402.48,217.97 r90 top
FID4 "Fiducial" Fiducial10-20 508.78,2294.74 r90 bottom
FID5 "Fiducial" Fiducial10-20 3412.32,2294.74 r90 bottom
FID6 "Fiducial" Fiducial10-20 3402.48,217.97 r90 bottom
H1 "NY PMS 440 0025 PH" "NY PMS 440 0025 PH" 3660,2250 r0 top
H2 "NY PMS 440 0025 PH" "NY PMS 440 0025 PH" 260,2250 r0 top
H3 "NY PMS 440 0025 PH" "NY PMS 440 0025 PH" 260,240 r0 top
H4 "NY PMS 440 0025 PH" "NY PMS 440 0025 PH" 3660,240 r0 top
H5 "1902C" Keystone_1902E 3660,2250 r180 bottom
H6 "1902C" Keystone_1902E 260,2250 r180 bottom
H7 "1902C" Keystone_1902E 260,240 r180 bottom
H8 "1902C" Keystone_1902E 3660.63,239.37 r180 bottom
J1 "282856-2" TE_282856-2 677.94,1202.1 r270 top
J2 "74655095R" FP-74655095R_CONN_TERM_10MM0_10MM0-MFG 3120,1586 r0 top
J3 "74655095R" FP-74655095R_CONN_TERM_10MM0_10MM0-MFG 3120,936 r0 top
J4 "TSW-112-07-G-S" TSW-112-07-G-S 1766.3,394.69 r0 top
L1 "XGL6060-332MEC" FP-XGL6060-332MEC_SMT_6MM51_6MM71-MFG 1111.01,1271 r0 bottom
L2 "VCUD128T-4R7MS8" FP-VCUD128T-4R7MS8_SMT_IND_13MM3_12MM8-MFG 2164.16,1271 r0 top
Logo1 "CE Mark" CE_Mark_5mm 2954.99,206.33 r180 bottom
Logo2 "Texas Instruments" TI_Stacked_Overlay_Small 1220.47,2322.83 r0 top
Logo3 "FCC disclaimer" FCC_disclaimer 2155,2411 r180 bottom
Logo4 "WEEE logo" WEEE_Minimum 2610.87,244.86 r180 bottom
R1 "ERJ-6GEY0R00V" 0805L 1396.44,1546.59 r270 bottom
R7 "AC0402FR-07100KL" 0402L 2095.26,473.76 r180 bottom
R8 "RC0603FR-07200KL" 0603L 1465.34,1005.25 r90 top
R9 "ERJPA2F1002X" 0402L 1453,937.2 r0 top
R10 "CRCW04021R00FKED" 0402L 2292.11,513.13 r0 bottom
R11 "KRL3216E-C-R001-J-T5" FP-KRL3216E-C-R001-J-T5_0612-MFG 2537,1261 r0 top
R12 "ERJPA2F1002X" 0402L 2114.94,1034.78 r0 bottom
R13 "CRCW040254K9FKED" 0402L 1483.82,860 r180 top
R14 "RK73Z1ETTP" 0402L 1904,955 r0 top
R15 "ERJ-2RKF49R9X" 0402L 1873,989 r0 top
R16 "CRCW040254K9FKED" 0402L 1538.27,842.1 r90 top
R17 "ERJ-2RKF49R9X" 0402L 2292.11,473.76 r0 bottom
R19 "CRCW040211K0FKED" 0402L 1734.29,798.59 r180 top
R20 "CRCW04028K66FKED" 0402L 1603.13,709.98 r90 top
R21 "CRCW040290K9FKED" 0402L 1643,749.35 r90 top
R22 "CRCW040223K7FKED" 0402L 1453,897.63 r0 top
R24 "CRCW040290K9FKED" 0402L 1524.39,719.82 r90 top
R25 "RK73Z1ETTP" 0402L 1849.2,778.87 r90 top
R26 "CRCW040254K9FKED" 0402L 1888.57,778.87 r90 top
R27 "RK73Z1ETTP" 0402L 1563.76,709.98 r90 top
R28 "ERA-2AEB4991X" 0402L 1681.87,749.35 r90 top
R29 "AC0402FR-07100KL" 0402L 1868,921 r0 top
SH-J1 "M7582-05" Harwin_M7582-05 1662,395 r180 top
SH-J2 "M7582-05" Harwin_M7582-05 2265,395 r180 top
TP1 "5019" Keystone_5019#1 677.94,1546.59 r0 top
TP2 "5019" Keystone_5019#1 677.94,847.77 r0 top
TP3 "5019" Keystone_5019#1 3120,1955 r0 top
TP4 "5019" Keystone_5019#2 3120,565 r0 top
U1 "LMG708B0VBTR" VBT0022B-MFG 1661,979 r180 top
ZZ1 "This Assembly Note is for PCB labels only" AssemblyNoteLabel 19.68,3357.28 r0 top
ZZ2 "These assemblies are ESD sensitive, ESD precautions shall be observed." AssemblyNote 19.68,3257.28 r0 top
ZZ3 "These assemblies must be clean and free from flux and all contaminants. Use of no clean flux is not acceptable." AssemblyNote 19.68,3157.28 r0 top
ZZ4 "These assemblies must comply with workmanship standards IPC-A-610 Class 2, unless otherwise specified." AssemblyNote 19.68,3061.02 r0 top
ZZ5 "Install Shunt Jumper SH-J1 onto J4 Pins 5-6" AssemblyNote 19.68,2952.76 r0 top
ZZ6 "Install Shunt Jumper SH-J2 onto J4 Pins 11-12" AssemblyNote 22,2844 r0 top

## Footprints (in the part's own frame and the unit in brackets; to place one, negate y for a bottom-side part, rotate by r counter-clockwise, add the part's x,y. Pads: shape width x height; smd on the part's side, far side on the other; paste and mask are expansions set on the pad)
0402_070 [mil] "SMD, 2-Leads, Body 1.2x0.7mm, Height 0.7mm"
  rect 15x24 smd: 1(-20,0) 2(20,0)
0402L [mm] "0402 from SM-752 data"
  rect 0.6x0.5 smd: 1(-0.5,0) 2(0.5,0)
0603L [mm] "0603 from SM-752 data"
  rect 0.8x0.85 smd: 1(-0.7,0) 2(0.7,0)
  silkscreen extent -0.07,-0.33 0.07,0.33
0805_HV [mil] "0805 with 30mil clearance between pads"
  rect 50x63 smd: 1(-40,0) 2(40,0)
  silkscreen extent -74,-40 74,40
0805L [mm] "0805 from SM-752 data"
  rect 1.1x1.4 smd: 1(-0.75,0) 2(0.75,0)
AssemblyNote [mil] "Assembly Note"
AssemblyNoteLabel [mil] "Assembly Note for PCB Labels"
CE_Mark_5mm [mil] "Minimum text height for CE Mark"
FCC_disclaimer [mil]
Fiducial10-20 [mm]
  round 1 smd mask+0: 1(0,0)
  Top Layer keep-out circle w1.178: c0,0 r0.5
FP-74655095R_CONN_TERM_10MM0_10MM0-MFG [mm]
  round 3.2 hole 1.85 paste+0 mask+0: 1(-4.435,-4.435) 1(-4.435,0) 1(-4.435,4.435) 1(0,-4.435) 1(0,4.435) 1(4.435,-4.435) 1(4.435,0) 1(4.435,4.435)
  round 5.2 hole 5.2 unplated paste+0 mask+0: ""(0,0)
  silkscreen extent -6.45,-6.45 6.45,6.45
FP-CGA6P3X7R1E226M250AB_1210-MFG [mm]
  rrect9% 1.1x2.2 smd paste+0 mask+0: 1(-1.65,0) 2(1.65,0)
  silkscreen extent -0.72,-1.4 0.72,1.4
FP-ECASD61C107M012KA0_2917-MFG [mm] "Recommended Land Pattern"
  rrect4% 2.4x2.8 smd paste+0 mask+0: 1(-3.2,0) 2(3.2,0)
  silkscreen extent -3.8,-2.25 5.3,2.25
FP-GCM32EC71A476KE02K_1210-MFG [mm]
  rrect9% 1.1x2.05 smd paste+0 mask+0: 1(-1.65,0) 2(1.65,0)
  silkscreen extent -0.72,-1.35 0.72,1.35
FP-GRM32EC72A106KE05L_1210-MFG [mm]
  rrect9% 1.1x2.05 smd paste+0 mask+0: 1(-1.65,0) 2(1.65,0)
  silkscreen extent -0.72,-1.35 0.72,1.35
FP-KRL3216E-C-R001-J-T5_0612-MFG [mm] "Recommended Land Pattern"
  rrect10% 1x3.4 smd paste+0 mask+0: 1(-0.7,0) 2(0.7,0)
  silkscreen extent -0.9,-2.07 0.9,2.07
FP-VCUD128T-4R7MS8_SMT_IND_13MM3_12MM8-MFG [mm] "Recommended Land Pattern"
  rrect3% 4x13.2 smd paste+0 mask+0: 1(-5.35,0) 2(5.35,0)
  silkscreen extent -8.02,-6.55 2.98,6.55
FP-XGL6060-332MEC_SMT_6MM51_6MM71-MFG [mm]
  rrect7% 1.43x5.5 smd paste+0 mask+0: 1(-2.02,0) 2(2.02,0)
  silkscreen extent -3.95,-3.45 3.35,3.45
Harwin_M7582-05 [mil] "Single Operation 2.54mm Pitch Open Top Jumper Socket"
IEC_HotSurface_Small [mil]
  silkscreen extent -107,-93 107,92
Keystone_1902E [mil] "Hex Standoff, 4-40 threaded, nylon"
  round 1 on Mech4: 0(0,0)
Keystone_5019#1 [mm] "Test Point, Miniature, SMT"
  rect 3.8x2.03 smd: 1(0,0)
  silkscreen extent -2.31,-1.42 2.31,1.42
Keystone_5019#2 [mm] "Test Point, Miniature, SMT"
  rect 3.8x2.03 smd: 1(-0.05,0.015)
  silkscreen extent -2.31,-1.42 2.31,1.42
"NY PMS 440 0025 PH" [mm] "4-40 nylon screw and mounting hole"
  round 8 hole 3.2: 1(0,0)
SM_RADIAL_G [mm] "10 x 10.2mm:  Panasonic G"
  rect 4.1x2 smd: 1(-4.35,0) 2(4.35,0)
  silkscreen extent -5.35,-5.35 5.35,5.35
TE_282856-2 [mm] "TH, 2-Leads, Body 10x10mm, Pitch 5mm"
  rect 1.9x1.9 hole 1.4: 1(-2.5,0)
  round 1.9 hole 1.4: 2(2.5,0)
  silkscreen extent -5.61,-5 5.5,5
TI_Stacked_Overlay_Small [mil]
TSW-112-07-G-S [mm] "Samtec 100mil, 1x12, 230 mil above insulator"
  rrect6% 1.65x1.65 hole 1.016 mask+0: 1(-13.97,0)
  round 1.65 hole 1.016 mask+0: 2(-11.43,0) 3(-8.89,0) 4(-6.35,0) 5(-3.81,0) 6(-1.27,0) 7(1.27,0) 8(3.81,0) 9(6.35,0) 10(8.89,0) 11(11.43,0) 12(13.97,0)
  silkscreen extent -15.24,-1.27 15.24,1.65
VBT0022B-MFG [mm] "Recommended Land Pattern"
  round 0.234 smd paste+0 mask+0: 1(-1.837,2.762)
  rrect40% 0.7x0.25 smd paste+0 mask+0: 2(-2.1,2.125) 3(-2.1,1.625) 4(-2.1,1.125) 5(-2.1,0.625) 6(-2.1,0.125) 10(2.1,0.125) 11(2.1,0.625) 12(2.1,1.125) 13(2.1,1.625) 14(2.1,2.125)
  rrect25% 0.8x2.35 smd paste-1000 mask+0: 7(-2.1,-1.675) 9(2.1,-1.675)
  rrect10% 2x3.15 smd paste-1000 mask+0: 8(0,-1.675)
  round 0.265 smd paste+0 mask+0: 15(1.875,2.675)
  rrect40% 0.25x0.7 smd paste+0 mask+0: 16(1.25,2.85) 17(0.75,2.85) 18(0.25,2.85) 19(-0.25,2.85) 20(-0.75,2.85) 21(-1.25,2.85)
  rrect10% 2.6x2.1 smd paste-1000 mask+0: 22(0,1.15)
  silkscreen extent -3.18,-3.37 2.6,3.3
WEEE_Minimum [mil] "WEEElie bin"
  silkscreen extent 22,-71 54,74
